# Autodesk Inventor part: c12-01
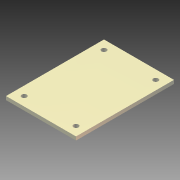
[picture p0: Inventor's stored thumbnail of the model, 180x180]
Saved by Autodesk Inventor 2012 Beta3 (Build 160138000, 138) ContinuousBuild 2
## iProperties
Created: 2011-01
Part Number: c12-01
Material: Steel
Document SubType Name: Modeling
Designer: Beta-8540w
Mass: 17231 g
Surface Area: 2089.64 cm^2
Volume: 2195.03 cm^3
Density: 7.85 g/cm^3
Author: Beta-8540w
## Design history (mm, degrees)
sketch "Sketch1"
  geometry: L1 (-111.085, -169.141)-(138.915, -169.141); L2 (138.915, -169.141)-(138.915, 180.859); L3 (138.915, 180.859)-(-111.085, 180.859); L4 (-111.085, 180.859)-(-111.085, -169.141); 4 further points
  constraints: 8 end point, 2 midpoint, 2 parallel, 1 horizontal, 1 horizontal alignment, 1 perpendicular, 1 vertical alignment, 1 other
  dimensions: "d0" = 250 distance of L3.end L2.end; "d1" = 350 distance of L2.end L1.end
extrude "Extrusion1" new body sketch "Sketch1" distance "d2" = 12.7; taper "d3" = 0 deg
sketch "Sketch2"
  geometry: L1 (-111.085, -169.141)-(138.915, -169.141) reference; L2 (138.915, -169.141)-(138.915, 180.859) reference; L3 (138.915, 180.859)-(-111.085, 180.859) reference; L4 (-111.085, 180.859)-(-111.085, -169.141) reference; L5 (-78.585, 148.359)-(106.415, 148.359); L6 (106.415, 148.359)-(106.415, -136.641); L7 (106.415, -136.641)-(-78.585, -136.641); L8 (-78.585, -136.641)-(-78.585, 148.359); 1 further point
  constraints: 8 end point, 3 other
  dimensions: "d4" = 185 distance of L5.start L5.end
hole "Hole1" sketch "Sketch2" at (-78.585, 148.359), (106.415, 148.359), (106.415, -136.641), (-78.585, -136.641) diameter "d5" = 18; stored, may be unused: countersink angle "d9" = 90 deg, drill point angle "d11" = 118 deg; dims "d6" = 6, "d7" = 4, "d8" = 10.75, "d10" = 8
body "Solid1"
